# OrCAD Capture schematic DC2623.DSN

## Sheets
1 PAGE2: size B; title: Single-Ended to Differential SAR Driver Board; rev: 0; note: DC2623A
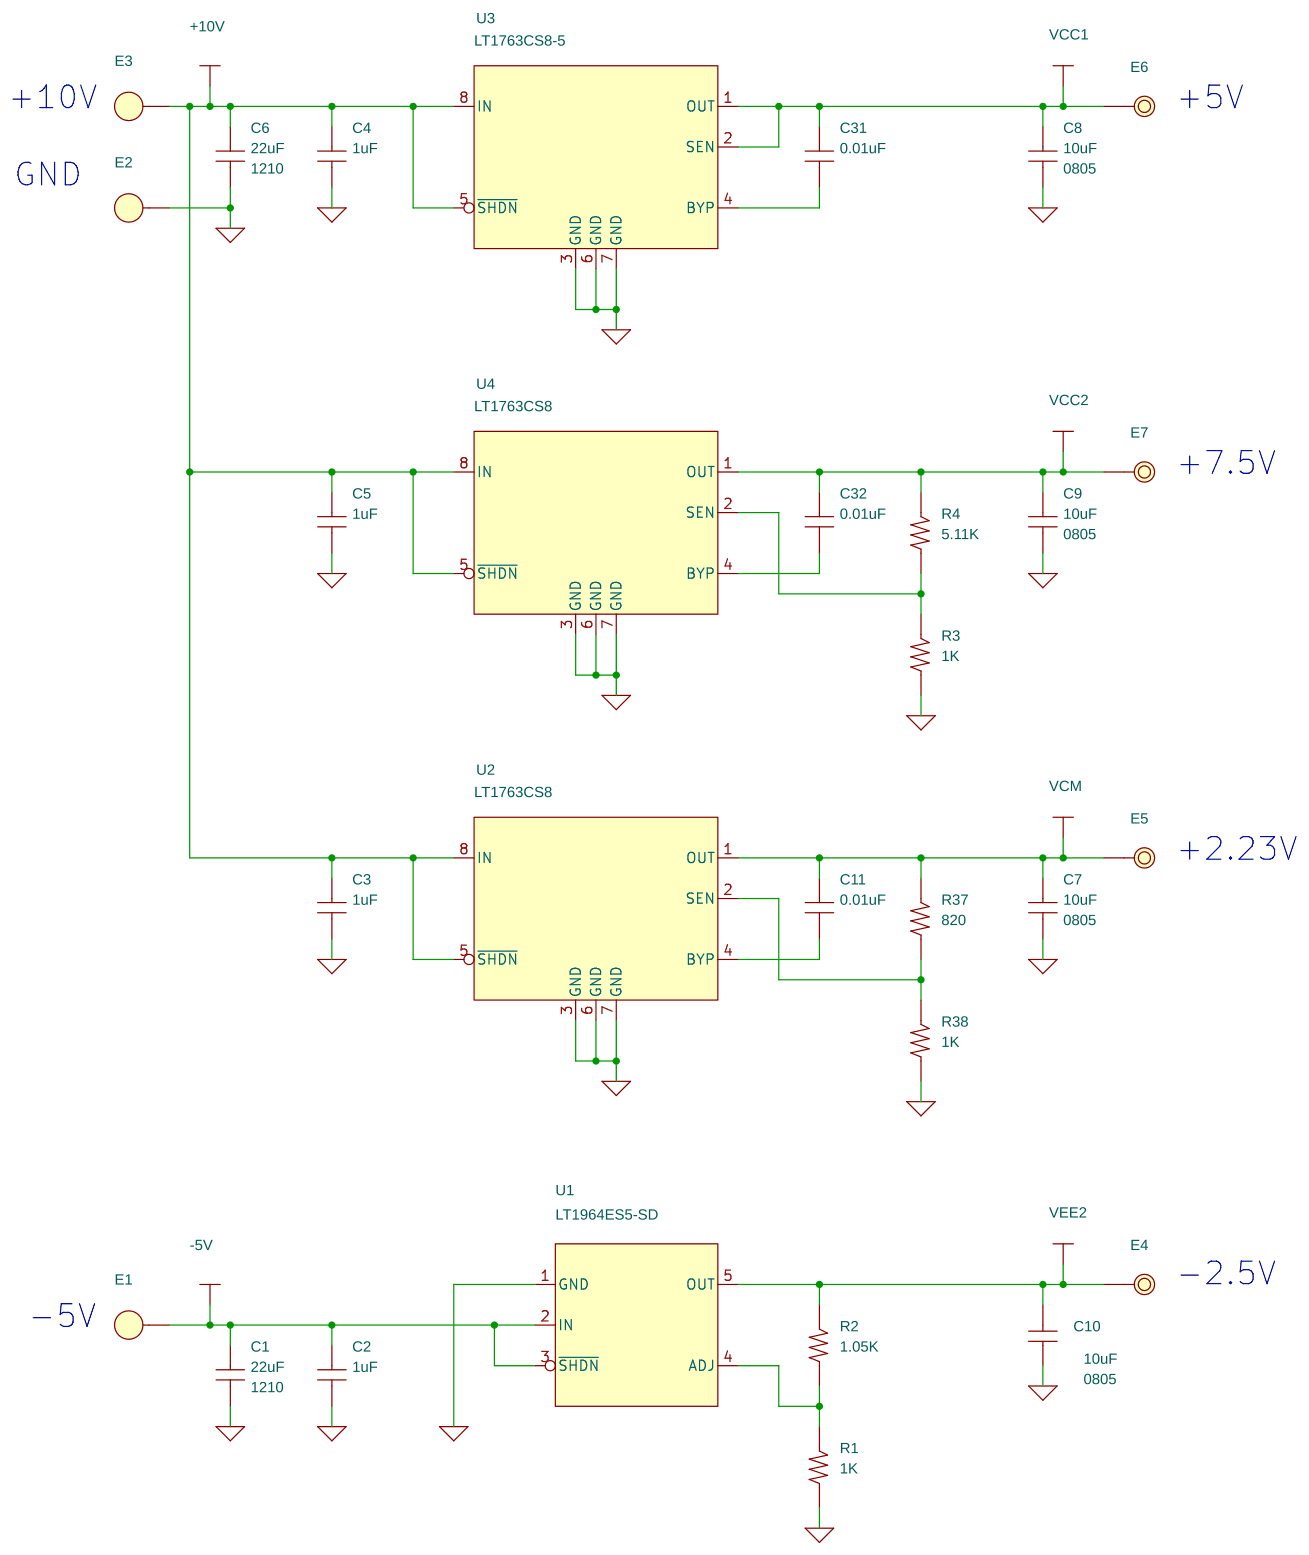
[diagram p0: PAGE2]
2 PAGE1: size B
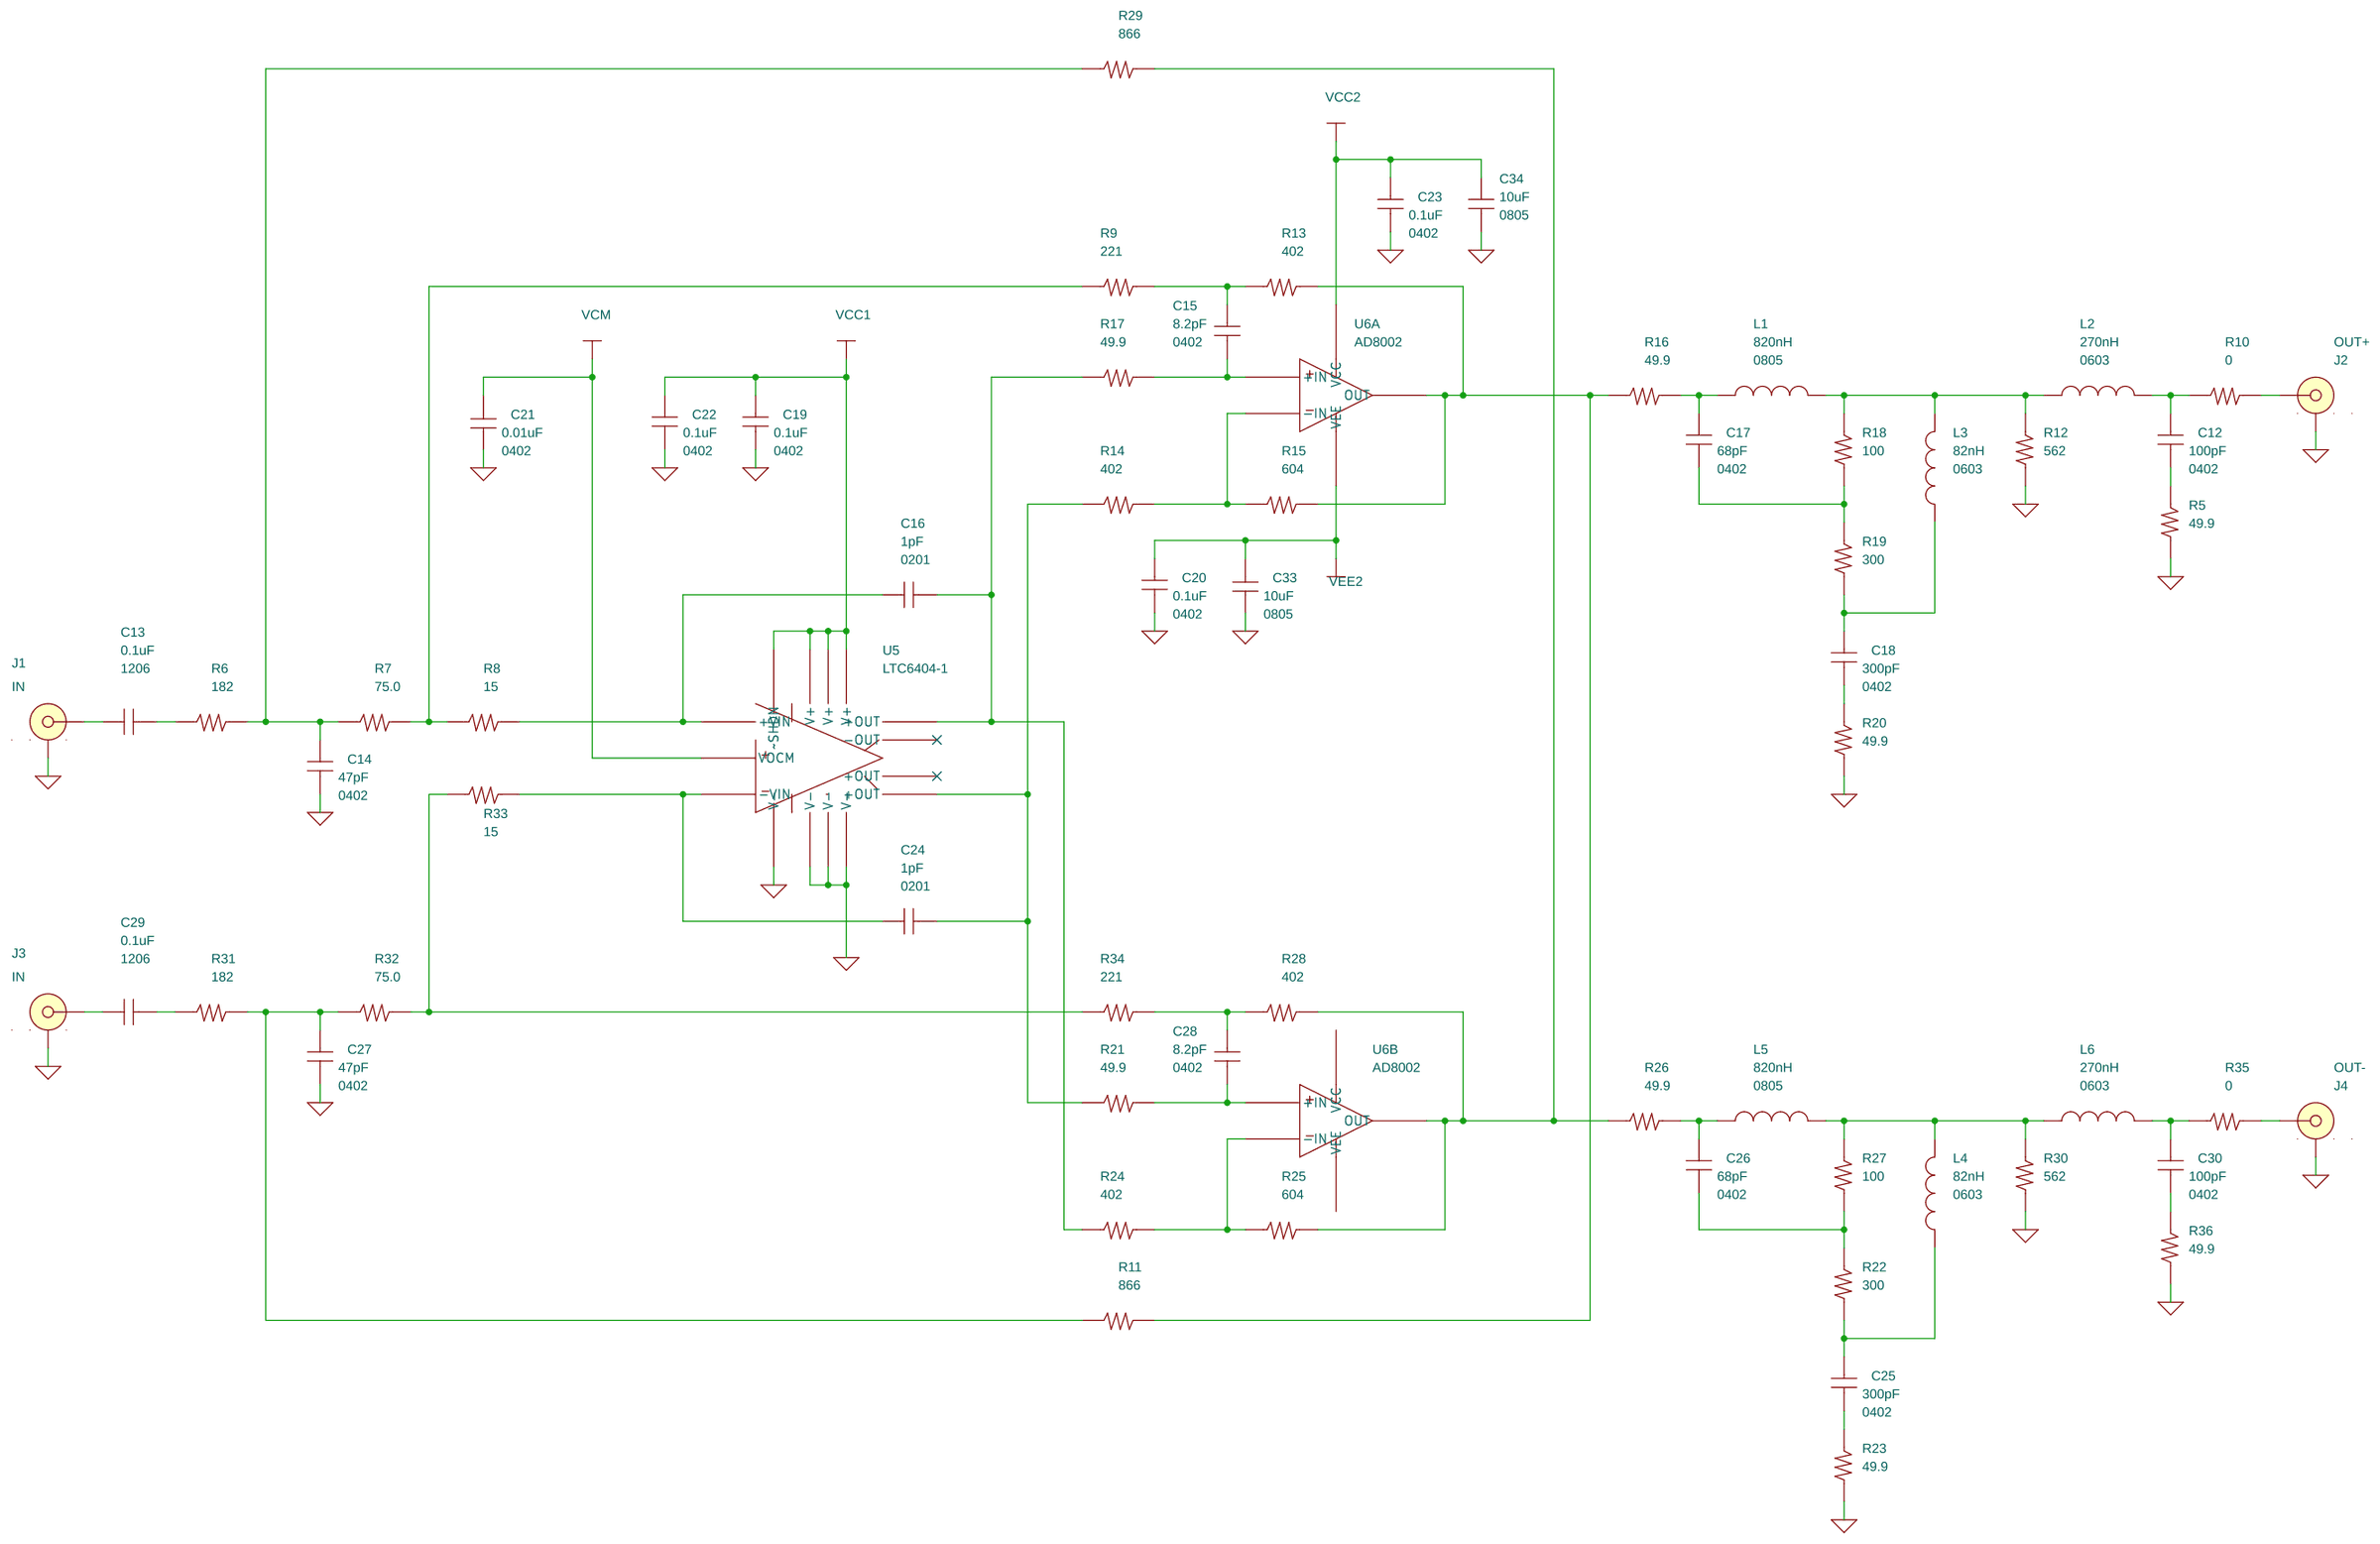
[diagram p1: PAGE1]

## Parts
sheet PAGE1
C12  100pF  [0402]
C13  0.1uF  [1206]
C14  47pF  [0402]
C15  8.2pF  [0402]
C16  1pF  [0201]
C17  68pF  [0402]
C18  300pF  [0402]
C19  0.1uF  [0402]
C20  0.1uF  [0402]
C21  0.01uF  [0402]
C22  0.1uF  [0402]
C23  0.1uF  [0402]
C24  1pF  [0201]
C25  300pF  [0402]
C26  68pF  [0402]
C27  47pF  [0402]
C28  8.2pF  [0402]
C29  0.1uF  [1206]
C30  100pF  [0402]
C33  10uF  [0805]
C34  10uF  [0805]
J1  CON-SMA-R-6LAYERS  [EFJOHNSON142-0701-851]
J2  CON-SMA-R-6LAYERS  [EFJOHNSON142-0701-851]
J3  CON-SMA-R-6LAYERS  [EFJOHNSON142-0701-851]
J4  CON-SMA-R-6LAYERS  [EFJOHNSON142-0701-851]
L1  820nH  [0805]
L2  270nH  [0603]
L3  82nH  [0603]
L4  82nH  [0603]
L5  820nH  [0805]
L6  270nH  [0603]
R5  49.9  [0402]
R6  182  [0402]
R7  75.0  [0402]
R8  15  [0402]
R9  221  [0402]
R10  0  [0402]
R11  866  [0402]
R12  562  [0402]
R13  402  [0402]
R14  402  [0402]
R15  604  [0402]
R16  49.9  [0402]
R17  49.9  [0402]
R18  100  [0402]
R19  300  [0402]
R20  49.9  [0402]
R21  49.9  [0402]
R22  300  [0402]
R23  49.9  [0402]
R24  402  [0402]
R25  604  [0402]
R26  49.9  [0402]
R27  100  [0402]
R28  402  [0402]
R29  866  [0402]
R30  562  [0402]
R31  182  [0402]
R32  75.0  [0402]
R33  15  [0402]
R34  221  [0402]
R35  0  [0402]
R36  49.9  [0402]
U5  LTC6404-1  [3X3QFN16]
U6  AD8002  [MS8]  (sections A,B)
sheet PAGE2
C1  22uF  [1210]
C2  1uF  [0603]
C3  1uF  [0603]
C4  1uF  [0603]
C5  1uF  [0603]
C6  22uF  [1210]
C7  10uF  [0805]
C8  10uF  [0805]
C9  10uF  [0805]
C10  10uF  [0805]
C11  0.01uF  [0603]
C31  0.01uF  [0603]
C32  0.01uF  [0603]
E1  MIL-MAX-2501  [MILL-MAX-2501]
E2  MIL-MAX-2501  [MILL-MAX-2501]
E3  MIL-MAX-2501  [MILL-MAX-2501]
E4  MILL-MAX-2308  [MILL-MAX-2308]
E5  MILL-MAX-2308  [MILL-MAX-2308]
E6  MILL-MAX-2308  [MILL-MAX-2308]
E7  MILL-MAX-2308  [MILL-MAX-2308]
R1  1K  [0603]
R2  1.05K  [0603]
R3  1K  [0603]
R4  5.11K  [0603]
R37  820  [0603]
R38  1K  [0603]
U1  LT1964ES5-SD  [SOT23-S5]
U2  LT1763CS8  [SO8]
U3  LT1763CS8-5  [SO8]
U4  LT1763CS8  [SO8]

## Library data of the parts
C7-C34 = CAP-NP
J1 J3 = CON_SMA-END_3: CONN, BNC, SMA 50-OHM EDGE-LANCH; Part Number: E.F.JOHNSON, 142-0701-851; label: IN
J2 = CON_SMA-END_3: CONN, BNC, SMA 50-OHM EDGE-LANCH; Part Number: E.F.JOHNSON, 142-0701-851; label: OUT+
J4 = CON_SMA-END_3: CONN, BNC, SMA 50-OHM EDGE-LANCH; Part Number: E.F.JOHNSON, 142-0701-851; label: OUT-
L1-L6 = INDUCTOR
R1-R38 = R
U5 = AD9685BD_2
U6 = AD648_TO_5
C1-C6 = CAP-NP: 1ST PART FIELD: 16V
E1-E3 = E-094
E4-E7 = E-064
U1 = LT1964ES5-SD-SOT23-5
U2-U4 = LT1763CS8-SO8

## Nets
+10V: C3.1 C4.1 C5.1 C6.1 E3.1(A) U2.5(~{SHDN}) U2.8(IN) U3.5(~{SHDN}) U3.8(IN) U4.5(~{SHDN}) U4.8(IN)
-5V: C1.1 C2.1 E1.1(A) U1.2(IN) U1.3(~{SHDN})
GND: C1.2 C2.2 C3.2 C4.2 C5.2 C6.2 C7.2 C8.2 C9.2 C10.1 C14.2 C19.2 C20.2 C21.1 C22.2 C23.2 C27.2 C33.1 C34.2 E2.1(A) J1.4(GND) J2.4(GND) J3.4(GND) J4.4(GND) R1.2 R3.2 R5.2 R12.2 R20.2 R23.2 R30.2 R36.2 R38.2 U1.1(GND) U2.3(GND) U2.6(GND) U2.7(GND) U3.3(GND) U3.6(GND) U3.7(GND) U4.3(GND) U4.6(GND) U4.7(GND) U5.3(V-) U5.9(V-) U5.12(V-) U5.PAD(V-)
SGND: J1.2(SGND) J1.3(SGND) J1.5(SGND) J2.2(SGND) J2.3(SGND) J2.5(SGND) J3.2(SGND) J3.3(SGND) J3.5(SGND) J4.2(SGND) J4.3(SGND) J4.5(SGND)
VCC1: C8.1 C19.1 C22.1 C31.1 E6.1(A) U3.1(OUT) U3.2(SEN) U5.1(~SHDN) U5.2(V+) U5.10(V+) U5.11(V+)
VCC2: C9.1 C23.1 C32.1 C34.1 E7.1(A) R4.1 U4.1(OUT) U6.8(VCC)
VEE2: C10.2 C20.1 C33.2 E4.1(A) R2.1 U1.5(OUT) U6.4(VEE)
VCM: C7.1 C11.1 C21.2 E5.1(A) R37.1 U2.1(OUT) U5.4(VOCM)
N6511538: R25.2 R26.1 R28.2 R29.2 U6.7(OUT)
N6511948: C14.1 R6.2 R7.1 R29.1
N6512094: C27.1 R11.1 R31.2 R32.1
N6512180: R11.2 R13.2 R15.2 R16.1 U6.1(OUT)
N6651781: C17.2 R18.2 R19.1
N6651867: C26.2 R22.1 R27.2
N6652011: C17.1 L1.1 R16.2
N6652020: C26.1 L5.1 R26.2
N6652256: L1.2 L2.1 L3.2 R12.1 R18.1
N6652370: L4.2 L5.2 L6.1 R27.1 R30.1
N6652464: C18.2 R20.1
N6652468: C18.1 L3.1 R19.2
N6652817: C25.2 R23.1
N6652821: C25.1 L4.1 R22.2
N6653547: C30.2 R36.1
N6653559: C30.1 L6.2 R35.1
N6653680: C12.2 R5.1
N6653708: C12.1 L2.2 R10.1
N6654889: J4.1(CENTER) R35.2
N6654965: J2.1(CENTER) R10.2
N6655480: C13.1 J1.1(CENTER)
N6660457: R1.1 R2.2 U1.4(ADJ)
N6660925: C31.2 U3.4(BYP)
N6664060: C29.1 J3.1(CENTER)
N6664645: R7.2 R8.1 R9.1
N6664655: R32.2 R33.1 R34.1
N6668265: R14.2 R15.1 U6.2(-IN)
N6668310: C15.2 R17.2 U6.3(+IN)
N6668345: C15.1 R9.2 R13.1
N6669164: R24.2 R25.1 U6.6(-IN)
N6669194: C28.2 R21.2 U6.5(+IN)
N6669202: C28.1 R28.1 R34.2
N6670157: C16.1 R8.2 U5.15(+VIN)
N6670161: C24.1 R33.2 U5.6(-VIN)
N6670544: C16.2 R17.1 R24.1 U5.14(+OUT)
N6670556: C24.2 R14.1 R21.1 U5.7(+OUT)
N6673856: R3.1 R4.2 U4.2(SEN)
N6674080: C32.2 U4.4(BYP)
N6675551: R37.2 R38.1 U2.2(SEN)
N6675733: C11.2 U2.4(BYP)
N6676068: C13.2 R6.1
N6676072: C29.2 R31.1

Not connected (* = marked no-connect by the designer): U5 8(+OUT)* 13(-OUT)*; U6 VCC VEE

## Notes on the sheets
sheet 1
- +10V
- +5V
- GND
- +7.5V
- +2.23V
- -2.5V
- -5V
